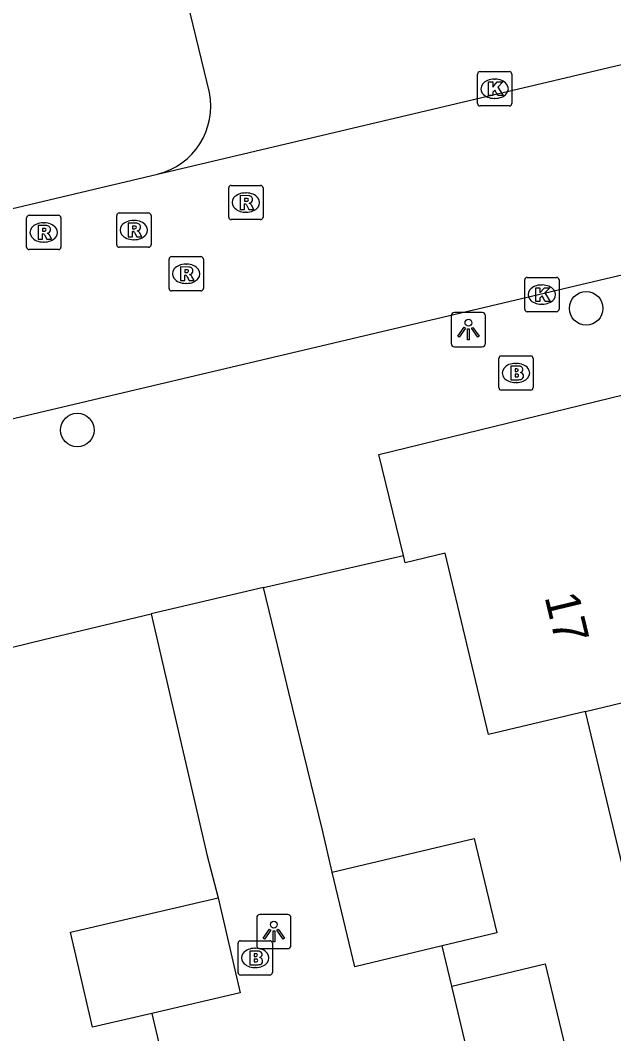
# Model space of a CAD drawing. Extents: x 158038 to 159242, y 380133 to 381214.
# Drawn here: x 158576.94 to 158594.23, y 380475.45 to 380505 of the extents above; entities that cross this region are included whole.
import ezdxf

# ---------------------------------------------------------------- set-up
doc = ezdxf.new("R2010")
doc.units = 0
for name, color, linetype in [('IMGEO_Boom', 7, 'Continuous'), ('IMGEO_Brandkraan', 7, 'Continuous'), ('IMGEO_Kolk', 7, 'Continuous'), ('IMGEO_Lichtpunt', 7, 'Continuous'), ('IMGEO_Pand', 7, 'Continuous'), ('IMGEO_Pand_nummerreeks', 7, 'Continuous'), ('IMGEO_Rijbaan_lokaal_open', 7, 'Continuous'), ('IMGEO_Rioolput', 7, 'Continuous'), ('IMGEO_Voetpad_open', 7, 'Continuous')]:
    doc.layers.add(name, color=color, linetype=linetype)

msp = doc.modelspace()

# ---------------------------------------------------------------- linework, layer by layer
at = {"layer": 'IMGEO_Boom'}
for centre in [(158593.432, 380496.6), (158578.6, 380493.05)]:
    msp.add_circle(centre, 0.489, dxfattribs=at)
at = {"layer": 'IMGEO_Brandkraan'}
for p, q in [((158590.96, 380495.216), (158591.812, 380495.216)), ((158590.885, 380494.29), (158590.885, 380495.142)), ((158591.373, 380494.996), (158591.398, 380494.996)), ((158591.886, 380495.142), (158591.886, 380494.29)), ((158591.396, 380494.436), (158591.371, 380494.436)), ((158591.812, 380494.216), (158590.96, 380494.216)), ((158583.284, 380477.232), (158583.284, 380478.084)), ((158583.359, 380478.158), (158584.211, 380478.158)), ((158584.285, 380478.084), (158584.285, 380477.232)), ((158583.772, 380477.938), (158583.797, 380477.938)), ((158584.211, 380477.158), (158583.359, 380477.158)), ((158583.795, 380477.378), (158583.77, 380477.378))]:
    msp.add_line(p, q, dxfattribs=at)
for points in [[(158590.96, 380495.216), (158591.812, 380495.216)], [(158590.885, 380494.29), (158590.885, 380495.142)], [(158591.233, 380494.916), (158591.233, 380494.516), (158591.446, 380494.516)], [(158591.464, 380494.916), (158591.233, 380494.916)], [(158591.886, 380495.142), (158591.886, 380494.29)], [(158591.412, 380494.835), (158591.358, 380494.835), (158591.358, 380494.759)], [(158591.358, 380494.759), (158591.411, 380494.759)], [(158591.42, 380494.683), (158591.358, 380494.683), (158591.358, 380494.602)], [(158591.358, 380494.602), (158591.42, 380494.602)], [(158591.812, 380494.216), (158590.96, 380494.216)], [(158583.284, 380477.232), (158583.284, 380478.084)], [(158583.359, 380478.158), (158584.211, 380478.158)], [(158584.285, 380478.084), (158584.285, 380477.232)], [(158583.632, 380477.858), (158583.632, 380477.458), (158583.845, 380477.458)], [(158583.863, 380477.858), (158583.632, 380477.858)], [(158583.811, 380477.777), (158583.757, 380477.777), (158583.757, 380477.701)], [(158583.757, 380477.701), (158583.81, 380477.701)], [(158583.819, 380477.625), (158583.757, 380477.625), (158583.757, 380477.544)], [(158583.757, 380477.544), (158583.819, 380477.544)], [(158584.211, 380477.158), (158583.359, 380477.158)]]:
    msp.add_lwpolyline(points, dxfattribs=at)
for centre, radius, start, end in [((158590.962, 380495.14), 0.0765, 91.552, 178.448), ((158590.962, 380495.14), 0.0765, 91.552, 178.448), ((158591.81, 380495.14), 0.0765, 1.552, 88.448), ((158591.81, 380495.14), 0.0765, 1.552, 88.448), ((158591.468, 380494.771), 0.145, 59.4692, 91.5367), ((158591.493, 380494.818), 0.0922, 285.5137, 58.1501), ((158591.413, 380494.797), 0.0379, 267.8285, 90.9355), ((158591.421, 380494.642), 0.0404, 269.8759, 90.5077), ((158591.498, 380494.626), 0.105, 301.3115, 78.989), ((158590.962, 380494.292), 0.0765, 181.552, 268.448), ((158590.962, 380494.292), 0.0765, 181.552, 268.448), ((158591.452, 380494.767), 0.251, 268.6676, 293.5347), ((158591.81, 380494.292), 0.0765, 271.552, 358.448), ((158591.81, 380494.292), 0.0765, 271.552, 358.448), ((158583.361, 380478.082), 0.0765, 91.552, 178.448), ((158583.361, 380478.082), 0.0765, 91.552, 178.448), ((158584.209, 380478.082), 0.0765, 1.552, 88.448), ((158584.209, 380478.082), 0.0765, 1.552, 88.448), ((158583.812, 380477.739), 0.0379, 267.8285, 90.9355), ((158583.867, 380477.713), 0.145, 59.4692, 91.5367), ((158583.892, 380477.76), 0.0922, 285.5137, 58.1501), ((158583.82, 380477.584), 0.0404, 269.8759, 90.5077), ((158583.851, 380477.709), 0.251, 268.6676, 293.5347), ((158583.897, 380477.568), 0.105, 301.3115, 78.989), ((158583.361, 380477.234), 0.0765, 181.552, 268.448), ((158583.361, 380477.234), 0.0765, 181.552, 268.448), ((158584.209, 380477.234), 0.0765, 271.552, 358.448), ((158584.209, 380477.234), 0.0765, 271.552, 358.448)]:
    msp.add_arc(centre, radius, start, end, dxfattribs=at)
for centre, major_axis, ratio, start_param, end_param in [((158591.372, 380494.716), (-0.387, 0.002), 0.722429, 4.712389, 7.853982), ((158591.397, 380494.716), (-0.39, 0.002), 0.717154, 1.570796, 4.712389), ((158583.771, 380477.658), (-0.387, 0.002), 0.722429, 4.712389, 7.853982), ((158583.796, 380477.658), (-0.39, 0.002), 0.717154, 1.570796, 4.712389)]:
    msp.add_ellipse(centre, major_axis=major_axis, ratio=ratio, start_param=start_param, end_param=end_param, dxfattribs=at)
at = {"layer": 'IMGEO_Kolk'}
for p, q in [((158590.263, 380502.577), (158590.263, 380503.429)), ((158590.338, 380503.503), (158591.19, 380503.503)), ((158591.264, 380503.429), (158591.264, 380502.577)), ((158590.751, 380503.283), (158590.776, 380503.283)), ((158590.774, 380502.723), (158590.749, 380502.723)), ((158591.19, 380502.503), (158590.338, 380502.503)), ((158591.639, 380496.575), (158591.639, 380497.427)), ((158591.714, 380497.501), (158592.566, 380497.501)), ((158592.127, 380497.281), (158592.152, 380497.281)), ((158592.64, 380497.427), (158592.64, 380496.575)), ((158592.15, 380496.721), (158592.125, 380496.721)), ((158592.566, 380496.501), (158591.714, 380496.501))]:
    msp.add_line(p, q, dxfattribs=at)
for points in [[(158590.263, 380502.577), (158590.263, 380503.429)], [(158590.338, 380503.503), (158591.19, 380503.503)], [(158591.264, 380503.429), (158591.264, 380502.577)], [(158590.584, 380503.203), (158590.707, 380503.203), (158590.707, 380503.052), (158590.837, 380503.203), (158591.001, 380503.203), (158590.855, 380503.052), (158591.008, 380502.803), (158590.856, 380502.803), (158590.771, 380502.967), (158590.707, 380502.9), (158590.707, 380502.803), (158590.584, 380502.803), (158590.584, 380503.203)], [(158591.19, 380502.503), (158590.338, 380502.503)], [(158591.639, 380496.575), (158591.639, 380497.427)], [(158591.714, 380497.501), (158592.566, 380497.501)], [(158592.64, 380497.427), (158592.64, 380496.575)], [(158591.96, 380497.201), (158592.083, 380497.201), (158592.083, 380497.05), (158592.213, 380497.201), (158592.377, 380497.201), (158592.231, 380497.05), (158592.384, 380496.801), (158592.232, 380496.801), (158592.147, 380496.965), (158592.083, 380496.898), (158592.083, 380496.801), (158591.96, 380496.801), (158591.96, 380497.201)], [(158592.566, 380496.501), (158591.714, 380496.501)]]:
    msp.add_lwpolyline(points, dxfattribs=at)
for centre, start, end in [((158590.34, 380503.427), 91.552, 178.448), ((158590.34, 380503.427), 91.552, 178.448), ((158591.188, 380503.427), 1.552, 88.448), ((158591.188, 380503.427), 1.552, 88.448), ((158590.34, 380502.579), 181.552, 268.448), ((158590.34, 380502.579), 181.552, 268.448), ((158591.188, 380502.579), 271.552, 358.448), ((158591.188, 380502.579), 271.552, 358.448), ((158591.716, 380497.425), 91.552, 178.448), ((158591.716, 380497.425), 91.552, 178.448), ((158592.564, 380497.425), 1.552, 88.448), ((158592.564, 380497.425), 1.552, 88.448), ((158591.716, 380496.577), 181.552, 268.448), ((158591.716, 380496.577), 181.552, 268.448), ((158592.564, 380496.577), 271.552, 358.448), ((158592.564, 380496.577), 271.552, 358.448)]:
    msp.add_arc(centre, 0.0765, start, end, dxfattribs=at)
for centre, major_axis, ratio, start_param, end_param in [((158590.75, 380503.003), (-0.387, 0.002), 0.722429, 4.712389, 7.853982), ((158590.775, 380503.003), (-0.39, 0.002), 0.717154, 1.570796, 4.712389), ((158592.126, 380497.001), (-0.387, 0.002), 0.722429, 4.712389, 7.853982), ((158592.151, 380497.001), (-0.39, 0.002), 0.717154, 1.570796, 4.712389)]:
    msp.add_ellipse(centre, major_axis=major_axis, ratio=ratio, start_param=start_param, end_param=end_param, dxfattribs=at)
at = {"layer": 'IMGEO_Lichtpunt'}
for p, q in [((158589.501, 380496.383), (158589.501, 380495.576)), ((158589.501, 380496.383), (158589.501, 380495.576)), ((158590.403, 380496.478), (158589.595, 380496.478)), ((158590.403, 380496.478), (158589.595, 380496.478)), ((158590.497, 380495.576), (158590.497, 380496.383)), ((158590.497, 380495.576), (158590.497, 380496.383)), ((158589.595, 380495.482), (158590.403, 380495.482)), ((158589.595, 380495.482), (158590.403, 380495.482)), ((158584.731, 380478.925), (158583.923, 380478.925)), ((158584.731, 380478.925), (158583.923, 380478.925)), ((158583.829, 380478.83), (158583.829, 380478.023)), ((158583.829, 380478.83), (158583.829, 380478.023)), ((158584.825, 380478.023), (158584.825, 380478.83)), ((158584.825, 380478.023), (158584.825, 380478.83)), ((158583.923, 380477.929), (158584.731, 380477.929)), ((158583.923, 380477.929), (158584.731, 380477.929))]:
    msp.add_line(p, q, dxfattribs=at)
for points in [[(158589.875, 380496.047), (158589.914, 380496.019), (158589.726, 380495.757), (158589.688, 380495.784), (158589.875, 380496.047)], [(158590.087, 380496.019), (158590.125, 380496.046), (158590.312, 380495.784), (158590.273, 380495.756), (158590.087, 380496.019)], [(158589.977, 380495.999), (158590.024, 380495.999), (158590.024, 380495.677), (158589.977, 380495.677), (158589.977, 380495.999)], [(158584.203, 380478.494), (158584.242, 380478.466), (158584.054, 380478.204), (158584.016, 380478.231), (158584.203, 380478.494)], [(158584.305, 380478.446), (158584.352, 380478.446), (158584.352, 380478.124), (158584.305, 380478.124), (158584.305, 380478.446)], [(158584.415, 380478.466), (158584.453, 380478.493), (158584.64, 380478.231), (158584.601, 380478.203), (158584.415, 380478.466)]]:
    msp.add_lwpolyline(points, dxfattribs=at)
for centre in [(158590, 380496.181), (158584.328, 380478.628)]:
    msp.add_circle(centre, 0.0994, dxfattribs=at)
for centre, start, end in [((158589.595, 380496.383), 90, 180), ((158589.595, 380496.383), 90, 180), ((158590.403, 380496.383), 0, 90), ((158590.403, 380496.383), 0, 90), ((158589.595, 380495.576), 180, 270), ((158589.595, 380495.576), 180, 270), ((158590.403, 380495.576), 270, 0), ((158590.403, 380495.576), 270, 360), ((158583.923, 380478.83), 90, 180), ((158583.923, 380478.83), 90, 180), ((158584.731, 380478.83), 0, 90), ((158584.731, 380478.83), 0, 90), ((158583.923, 380478.023), 180, 270), ((158583.923, 380478.023), 180, 270), ((158584.731, 380478.023), 270, 0), ((158584.731, 380478.023), 270, 360)]:
    msp.add_arc(centre, 0.0946, start, end, dxfattribs=at)
at = {"layer": 'IMGEO_Pand'}
for points in [[(158588.105, 380489.392), (158587.386, 380492.338), (158597.49, 380494.805)], [(158593.408, 380484.847), (158590.586, 380484.17), (158589.317, 380489.464), (158588.156, 380489.181), (158588.105, 380489.392)], [(158593.408, 380484.847), (158596.399, 380485.563), (158595.674, 380488.584), (158598.824, 380489.341)], [(158597.503, 380480.078), (158594.712, 380479.408), (158593.408, 380484.847)], [(158586.03, 380480.156), (158590.169, 380481.142), (158590.825, 380478.387), (158589.235, 380478.009)], [(158589.235, 380478.009), (158586.686, 380477.402), (158586.03, 380480.156)], [(158580.767, 380476.037), (158579.045, 380475.635), (158578.399, 380478.404), (158582.701, 380479.408)], [(158582.701, 380479.408), (158583.347, 380476.639), (158580.767, 380476.037)], [(158589.516, 380476.832), (158592.239, 380477.481), (158593.224, 380473.35)], [(158590.501, 380472.7), (158589.516, 380476.832)]]:
    msp.add_lwpolyline(points, dxfattribs=at)
at = {"layer": 'IMGEO_Rijbaan_lokaal_open'}
for points in [[(158580.936, 380500.512), (158623.075, 380510.483)], [(158617.159, 380502.945), (158612.772, 380501.896), (158570.966, 380492.021)], [(158569.608, 380497.828), (158580.936, 380500.512)]]:
    msp.add_lwpolyline(points, dxfattribs=at)
at = {"layer": 'IMGEO_Rioolput'}
for p, q in [((158583.087, 380500.186), (158583.939, 380500.186)), ((158583.012, 380499.26), (158583.012, 380500.112)), ((158583.5, 380499.966), (158583.525, 380499.966)), ((158584.013, 380500.112), (158584.013, 380499.26)), ((158577.195, 380499.313), (158578.047, 380499.313)), ((158579.747, 380498.456), (158579.747, 380499.308)), ((158579.822, 380499.382), (158580.674, 380499.382)), ((158580.748, 380499.308), (158580.748, 380498.456)), ((158583.523, 380499.406), (158583.498, 380499.406)), ((158577.12, 380498.387), (158577.12, 380499.239)), ((158577.608, 380499.093), (158577.633, 380499.093)), ((158578.121, 380499.239), (158578.121, 380498.387)), ((158580.235, 380499.162), (158580.26, 380499.162)), ((158583.939, 380499.186), (158583.087, 380499.186)), ((158577.631, 380498.533), (158577.606, 380498.533)), ((158580.258, 380498.602), (158580.233, 380498.602)), ((158578.047, 380498.313), (158577.195, 380498.313)), ((158580.674, 380498.382), (158579.822, 380498.382)), ((158581.347, 380498.107), (158582.199, 380498.107)), ((158581.272, 380497.181), (158581.272, 380498.033)), ((158581.76, 380497.887), (158581.785, 380497.887)), ((158582.273, 380498.033), (158582.273, 380497.181)), ((158581.783, 380497.327), (158581.758, 380497.327)), ((158582.199, 380497.107), (158581.347, 380497.107))]:
    msp.add_line(p, q, dxfattribs=at)
for points in [[(158583.087, 380500.186), (158583.939, 380500.186)], [(158583.012, 380499.26), (158583.012, 380500.112)], [(158583.601, 380499.884), (158583.349, 380499.886), (158583.349, 380499.486)], [(158584.013, 380500.112), (158584.013, 380499.26)], [(158583.349, 380499.486), (158583.473, 380499.486), (158583.473, 380499.648), (158583.484, 380499.648)], [(158583.527, 380499.805), (158583.473, 380499.805), (158583.473, 380499.724)], [(158583.473, 380499.724), (158583.525, 380499.724)], [(158583.531, 380499.619), (158583.602, 380499.486), (158583.742, 380499.486), (158583.677, 380499.612)], [(158577.195, 380499.313), (158578.047, 380499.313)], [(158579.747, 380498.456), (158579.747, 380499.308)], [(158579.822, 380499.382), (158580.674, 380499.382)], [(158580.748, 380499.308), (158580.748, 380498.456)], [(158577.12, 380498.387), (158577.12, 380499.239)], [(158577.709, 380499.011), (158577.457, 380499.013), (158577.457, 380498.613)], [(158578.121, 380499.239), (158578.121, 380498.387)], [(158580.336, 380499.08), (158580.084, 380499.082), (158580.084, 380498.682)], [(158580.262, 380499.001), (158580.208, 380499.001), (158580.208, 380498.92)], [(158583.939, 380499.186), (158583.087, 380499.186)], [(158577.457, 380498.613), (158577.581, 380498.613), (158577.581, 380498.775), (158577.592, 380498.775)], [(158577.635, 380498.932), (158577.581, 380498.932), (158577.581, 380498.851)], [(158577.581, 380498.851), (158577.633, 380498.851)], [(158577.639, 380498.746), (158577.71, 380498.613), (158577.85, 380498.613), (158577.785, 380498.739)], [(158580.084, 380498.682), (158580.208, 380498.682), (158580.208, 380498.844), (158580.219, 380498.844)], [(158580.208, 380498.92), (158580.26, 380498.92)], [(158580.266, 380498.815), (158580.337, 380498.682), (158580.477, 380498.682), (158580.412, 380498.808)], [(158578.047, 380498.313), (158577.195, 380498.313)], [(158580.674, 380498.382), (158579.822, 380498.382)], [(158581.347, 380498.107), (158582.199, 380498.107)], [(158581.272, 380497.181), (158581.272, 380498.033)], [(158582.273, 380498.033), (158582.273, 380497.181)], [(158581.861, 380497.805), (158581.609, 380497.807), (158581.609, 380497.407)], [(158581.609, 380497.407), (158581.733, 380497.407), (158581.733, 380497.569), (158581.744, 380497.569)], [(158581.787, 380497.726), (158581.733, 380497.726), (158581.733, 380497.645)], [(158581.733, 380497.645), (158581.785, 380497.645)], [(158581.791, 380497.54), (158581.862, 380497.407), (158582.002, 380497.407), (158581.937, 380497.533)], [(158582.199, 380497.107), (158581.347, 380497.107)]]:
    msp.add_lwpolyline(points, dxfattribs=at)
for centre, radius, start, end in [((158583.089, 380500.11), 0.0765, 91.552, 178.448), ((158583.089, 380500.11), 0.0765, 91.552, 178.448), ((158583.937, 380500.11), 0.0765, 1.552, 88.448), ((158583.937, 380500.11), 0.0765, 1.552, 88.448), ((158583.6, 380499.774), 0.109, 350.3612, 89.416), ((158583.483, 380499.595), 0.0533, 26.0293, 88.6989), ((158583.509, 380499.913), 0.19, 274.7715, 282.9687), ((158583.533, 380499.709), 0.0964, 77.0061, 93.1865), ((158583.547, 380499.766), 0.0378, 276.6634, 79.6772), ((158583.598, 380499.774), 0.112, 277.5842, 350.9817), ((158583.582, 380499.559), 0.108, 29.5134, 73.7905), ((158577.197, 380499.237), 0.0765, 91.552, 178.448), ((158577.197, 380499.237), 0.0765, 91.552, 178.448), ((158578.045, 380499.237), 0.0765, 1.552, 88.448), ((158578.045, 380499.237), 0.0765, 1.552, 88.448), ((158579.824, 380499.306), 0.0765, 91.552, 178.448), ((158579.824, 380499.306), 0.0765, 91.552, 178.448), ((158580.672, 380499.306), 0.0765, 1.552, 88.448), ((158580.672, 380499.306), 0.0765, 1.552, 88.448), ((158577.708, 380498.901), 0.109, 350.3612, 89.416), ((158580.268, 380498.905), 0.0964, 77.0061, 93.1865), ((158580.282, 380498.962), 0.0378, 276.6634, 79.6772), ((158580.335, 380498.97), 0.109, 350.3612, 89.416), ((158583.089, 380499.262), 0.0765, 181.552, 268.448), ((158583.089, 380499.262), 0.0765, 181.552, 268.448), ((158583.937, 380499.262), 0.0765, 271.552, 358.448), ((158583.937, 380499.262), 0.0765, 271.552, 358.448), ((158577.591, 380498.722), 0.0533, 26.0293, 88.6989), ((158577.617, 380499.04), 0.19, 274.7715, 282.9687), ((158577.641, 380498.836), 0.0964, 77.0061, 93.1865), ((158577.655, 380498.893), 0.0378, 276.6634, 79.6772), ((158577.706, 380498.901), 0.112, 277.5842, 350.9817), ((158577.69, 380498.686), 0.108, 29.5134, 73.7905), ((158580.218, 380498.791), 0.0533, 26.0293, 88.6989), ((158580.244, 380499.109), 0.19, 274.7715, 282.9687), ((158580.333, 380498.97), 0.112, 277.5842, 350.9817), ((158580.317, 380498.755), 0.108, 29.5134, 73.7905), ((158579.824, 380498.458), 0.0765, 181.552, 268.448), ((158579.824, 380498.458), 0.0765, 181.552, 268.448), ((158580.672, 380498.458), 0.0765, 271.552, 358.448), ((158580.672, 380498.458), 0.0765, 271.552, 358.448), ((158577.197, 380498.389), 0.0765, 181.552, 268.448), ((158577.197, 380498.389), 0.0765, 181.552, 268.448), ((158578.045, 380498.389), 0.0765, 271.552, 358.448), ((158578.045, 380498.389), 0.0765, 271.552, 358.448), ((158581.349, 380498.031), 0.0765, 91.552, 178.448), ((158581.349, 380498.031), 0.0765, 91.552, 178.448), ((158582.197, 380498.031), 0.0765, 1.552, 88.448), ((158582.197, 380498.031), 0.0765, 1.552, 88.448), ((158581.743, 380497.516), 0.0533, 26.0293, 88.6989), ((158581.769, 380497.834), 0.19, 274.7715, 282.9687), ((158581.793, 380497.63), 0.0964, 77.0061, 93.1865), ((158581.807, 380497.687), 0.0378, 276.6634, 79.6772), ((158581.86, 380497.695), 0.109, 350.3612, 89.416), ((158581.858, 380497.695), 0.112, 277.5842, 350.9817), ((158581.842, 380497.48), 0.108, 29.5134, 73.7905), ((158581.349, 380497.183), 0.0765, 181.552, 268.448), ((158581.349, 380497.183), 0.0765, 181.552, 268.448), ((158582.197, 380497.183), 0.0765, 271.552, 358.448), ((158582.197, 380497.183), 0.0765, 271.552, 358.448)]:
    msp.add_arc(centre, radius, start, end, dxfattribs=at)
for centre, major_axis, ratio, start_param, end_param in [((158583.499, 380499.686), (-0.387, 0.002), 0.722429, 4.712389, 7.853982), ((158583.524, 380499.686), (-0.39, 0.002), 0.717154, 1.570796, 4.712389), ((158577.607, 380498.813), (-0.387, 0.002), 0.722429, 4.712389, 7.853982), ((158577.632, 380498.813), (-0.39, 0.002), 0.717154, 1.570796, 4.712389), ((158580.234, 380498.882), (-0.387, 0.002), 0.722429, 4.712389, 7.853982), ((158580.259, 380498.882), (-0.39, 0.002), 0.717154, 1.570796, 4.712389), ((158581.759, 380497.607), (-0.387, 0.002), 0.722429, 4.712389, 7.853982), ((158581.784, 380497.607), (-0.39, 0.002), 0.717154, 1.570796, 4.712389)]:
    msp.add_ellipse(centre, major_axis=major_axis, ratio=ratio, start_param=start_param, end_param=end_param, dxfattribs=at)
at = {"layer": 'IMGEO_Voetpad_open'}
for points in [[(158582.453, 380502.891), (158581.739, 380505.83), (158620.043, 380514.915), (158620.771, 380511.94)], [(158584.029, 380488.461), (158588.105, 380489.392)], [(158584.029, 380488.461), (158580.749, 380487.695)], [(158586.03, 380480.156), (158585.75, 380481.384), (158584.768, 380485.397), (158584.435, 380486.777), (158584.029, 380488.461)], [(158576.713, 380486.721), (158577.624, 380486.941), (158580.749, 380487.695)], [(158580.749, 380487.695), (158582.389, 380480.638), (158582.701, 380479.408)], [(158589.516, 380476.832), (158589.235, 380478.009)], [(158580.767, 380476.037), (158581.051, 380474.84)]]:
    msp.add_lwpolyline(points, dxfattribs=at)
msp.add_arc((158580.447, 380502.497), 2.044, 283.8279, 11.1238, dxfattribs=at)

# ---------------------------------------------------------------- texts
at = {"layer": 'IMGEO_Pand_nummerreeks'}
msp.add_text('17', height=1, rotation=283.4794, dxfattribs=at).set_placement((158592.214, 380488.19))

doc.saveas('drawing.dxf')
